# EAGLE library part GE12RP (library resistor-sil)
SIL RESISTOR
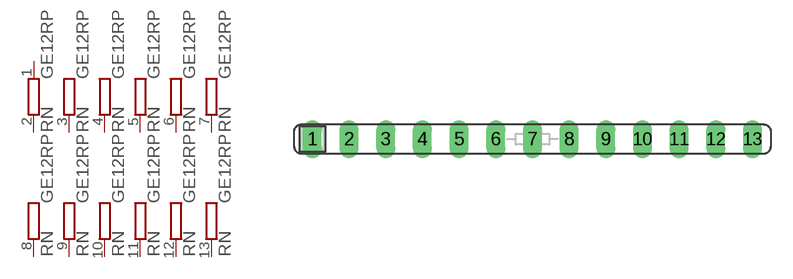
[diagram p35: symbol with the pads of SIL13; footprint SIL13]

Designator prefix RN; gates A=R-PV B=R-PV1 C=R-PV1 D=R-PV1 E=R-PV1 F=R-PV1 G=R-PV1 H=R-PV1 I=R-PV1 J=R-PV1 K=R-PV1 L=R-PV1

## GE12RP (OC_FARNELL: unknown; OC_NEWARK: unknown)  [SIL13]
1  A:1  pas
2  A:2  pas
3  B:2  pas
4  C:2  pas
5  D:2  pas
6  E:2  pas
7  F:2  pas
8  G:2  pas
9  H:2  pas
10  I:2  pas
11  J:2  pas
12  K:2  pas
13  L:2  pas

## Footprint SIL13 (pad centres in mm)
Single In Line
drill 0.813 long: 1 -15.24,0; 2 -12.7,0; 3 -10.16,0; 4 -7.62,0; 5 -5.08,0; 6 -2.54,0; 7 0,0; 8 2.54,0; 9 5.08,0; 10 7.62,0; 11 10.16,0; 12 12.7,0; 13 15.24,0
